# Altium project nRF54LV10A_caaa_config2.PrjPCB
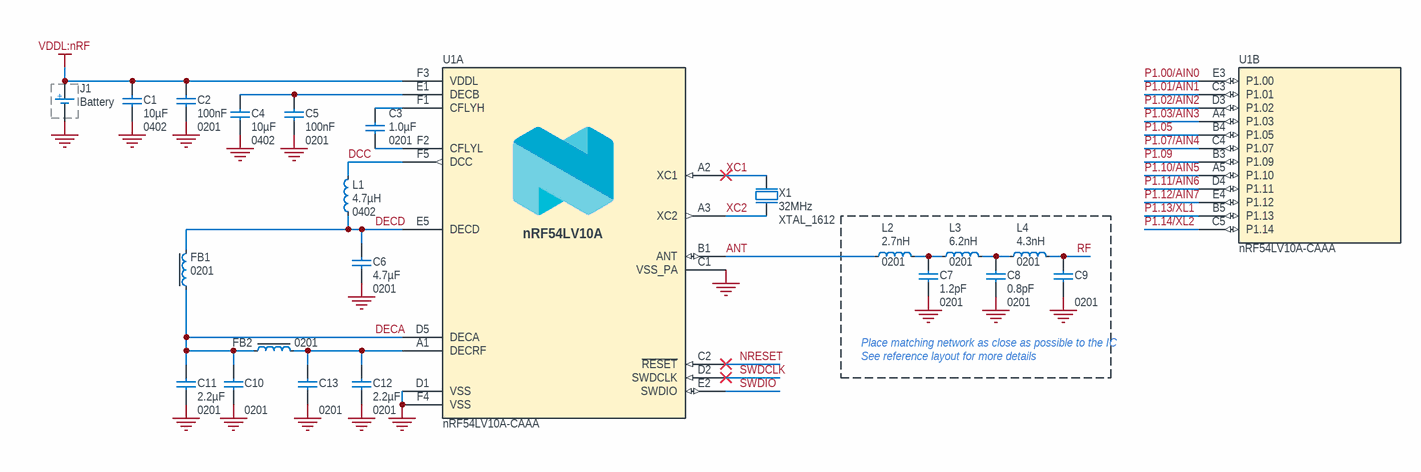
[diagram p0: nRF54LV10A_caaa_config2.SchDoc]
RefLayoutTitle: VDDL:nRF supplied by 1.5 V battery, Enabled DC/DC, 4-Layer PCB; Revision: 0.6; DrawnBy: DABA; Device: nRF54LV10A-CAAA; Config: 2; Classification: Public
1 sheet, 22 parts. Net scope: strictly hierarchical (ports join the sheet entries above them; power ports are local).
Board file: nRF54LV10A_caaa_config2.PcbDoc

## Sheet nRF54LV10A_caaa_config2.SchDoc
size A4; PCAName: Reference Layout; Organization: Nordic Semiconductor; SheetNumber: 1; SheetTotal: 1; DocumentSize: A4; Device: nRF54LV10A-CAAA; Classification: Confidential; Config: 2

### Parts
C1  10µF  Footprint Doc: 0402  [CAPC1005X04L]
C2  100nF  Footprint Doc: 0201  [CAPC0603X03L_C]
C3  1.0µF  Footprint Doc: 0201  [CAPC0603X03L_C]
C4  10µF  Footprint Doc: 0402  [CAPC1005X04L]
C5  100nF  Footprint Doc: 0201  [CAPC0603X03L_C]
C6  4.7µF  Footprint Doc: 0201  [CAPC0603X03L_C]
C7  1.2pF  Footprint Doc: 0201  [CAPC0603X03L_C]
C8  0.8pF  Footprint Doc: 0201  [CAPC0603X03L_C]
C9  Footprint Doc: 0201  [CAPC0603X03L_C]  (hidden comment: 0.3pF)
C10  Footprint Doc: 0201  [CAPC0603X03L_C]  (hidden comment: 2.2µF)
C11  Footprint Doc: 0201  [CAPC0603X03L_C]  (hidden comment: 2.2µF)
C12  Footprint Doc: 0201  [CAPC0603X03L_C]  (hidden comment: 2.2µF)
C13  Footprint Doc: 0201  [CAPC0603X03L_C]  (hidden comment: 2.2µF)
FB1  Footprint Doc: 0201  [INDC0603X03L_C]  (hidden comment: 120R/0.2A)
FB2  Footprint Doc: 0201  [INDC0603X03L_C]  (hidden comment: 120R/0.2A)
J1  Battery  [TP_2x1mm_TH]  (graphical)
L1  4.7µH  Footprint Doc: 0402  [INDDFN10X06X08L31X32L]
L2  2.7nH  Footprint Doc: 0201  [INDC0603X03L_C]
L3  6.2nH  Footprint Doc: 0201  [INDC0603X03L_C]
L4  4.3nH  Footprint Doc: 0201  [INDC0603X03L_C]
U1  nRF54LV10A-CAAA  [BGA29CP35_5X6_239X201X45B20]  (parts A,B of 2)
X1  32MHz  Footprint Doc: XTAL_1612  [BT-XTAL_1612]

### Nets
GND: C1.1 C2.2 C4.1 C5.2 C6.1 C7.1 C8.1 C9.1 C10.2 C11.1 C12.1 C13.2 J1.1(GND) U1.C1(VSS_PA) U1.D1(VSS) U1.F4(VSS) X1.2(GND) X1.4(GND)
VDDL:nRF: C1.2 C2.1 J1.2(V+) U1.F3(VDDL)
ANT: L2.1 U1.B1(ANT)
DCC: L1.2 U1.F5(DCC)
DECA: C10.1 C11.2 FB1.2 FB2.2 U1.D5(DECA)
DECD: C6.2 FB1.1 L1.1 U1.E5(DECD)
NRESET: U1.C2(~{RESET})
P1.00/AIN0: U1.E3(P1.00)
P1.01/AIN1: U1.C3(P1.01)
P1.02/AIN2: U1.D3(P1.02)
P1.03/AIN3: U1.A4(P1.03)
P1.05: U1.B4(P1.05)
P1.07/AIN4: U1.C4(P1.07)
P1.09: U1.B3(P1.09)
P1.10/AIN5: U1.A5(P1.10)
P1.11/AIN6: U1.D4(P1.11)
P1.12/AIN7: U1.E4(P1.12)
P1.13/XL1: U1.B5(P1.13)
P1.14/XL2: U1.C5(P1.14)
RF: C9.2 L4.2
SWDCLK: U1.D2(SWDCLK)
SWDIO: U1.E2(SWDIO)
XC1: U1.A2(XC1) X1.1(inp)
XC2: U1.A3(XC2) X1.3(out)
NetC3_1: C3.1 U1.F2(CFLYL)
NetC3_2: C3.2 U1.F1(CFLYH)
NetC4_2: C4.2 C5.1 U1.E1(DECB)
NetC7_2: C7.2 L2.2 L3.1
NetC8_2: C8.2 L3.2 L4.1
NetC12_2: C12.2 C13.1 FB2.1 U1.A1(DECRF)

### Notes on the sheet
- See reference layout for more details
- Place matching network as close as possible to the IC

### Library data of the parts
C1 C4 = C0402-10µF-6.3V-X6S: Capacitor, X6S, ±20%, 6.3V; Manufacturer: N.A.; Part number NEMS: 100200478; Component Status: Active; Pad Count: 2
C2 C5 = C0201-100n-10V-X7R: Capacitor, X7R, ±10%, 100nF, 10V; Manufacturer: N.A.; Part number NEMS: 100200469; Pad Count: 2; Component Status: Active
C3 = C0201-1µ0-6.3V: Capacitor, Ceramic, X5R, ±20%, 6.3V; Manufacturer: Murata; Manufacturer Part Number: GRM033R60J105MEA2D; Part number NEMS: 100200387; Component Status: Active; Pad Count: 2; Artikkelnr Noca: N.A.
C6 = C0201-4.7µ-6V3-X5R-GRM035R60J475ME15J: Capacitor, Ceramic, X5R, ±20%, 6.3V; Manufacturer: Murata; Part number NEMS: 100200685; Component Status: Active; Pad Count: 2; Note: -55°C ~ 85°C; Artikkelnr Noca: N.A.
C7 = C0201-1.2p-HQ-Murata: Capacitor, NP0, ±0.05pF, 50V; Manufacturer: Murata; Manufacturer Part Number: GJM0335C1H1R2WB01D; Part number NEMS: 100200457; Component Status: Active; Pad Count: 2; Artikkelnr Noca: N.A.
C8 = C0201-0.8p: Capacitor, NP0, ±0.05pF, 50V; Manufacturer: Murata; Manufacturer Part Number: GJM0335C1HR80WB01; Part number IPS: 80000001975; Part number NEMS: 100200012; Component Status: Active; Pad Count: 2; Artikkelnr Noca: N.A.
C9 = C0201-0.3p-50V-GRM0335C1HR30BA01: Capacitor, C0G, ±0.1pF, 50V; Manufacturer: Murata; Part number NEMS: 100200650; Component Status: Active; Pad Count: 2; Artikkelnr Noca: N.A.
C10-C13 = C0201-2µ2-2.5V-X6T-GRM033D80E225ME47D: Capacitor, Ceramic, 2.2µF 2.5V X6T 0201,±20%; Manufacturer: Murata; Part number NEMS: 100200527; Component Status: Active; Pad Count: 2; Note: 2.5V, 20%, X6T; Artikkelnr Noca: N.A.
FB1 FB2 = FB0201-120R@100M-200mA-BLM03AG121SN1D: Ferrite Bead, 120 Ohm @ 100MHz, 200mA, 500 mOhm Max; Manufacturer: Murata; Part number NEMS: 100300419; Component Status: Active; Pad Count: 2; Artikkelnr Noca: N.A.
J1 = Battery_TP: Manufacturer: N.A.; Part number NEMS: 101800006; Component Status: Active; Pad Count: 3
L1 = L0402-4µ7-PLEA67BCA4R7M-1PT00: Inductor, 300mA, ±20%, 1.08R; Manufacturer: TDK Corporation; Part number NEMS: 100300441; Component Status: Active; Pad Count: 2; Note: Power Inductor ±20%; Artikkelnr Noca: N.A.
L2 = L0201-2n7-HQ-Murata: Inductor, 600mA, ±0.1ｎH, 120mOhm; Manufacturer: Murata; Manufacturer Part Number: LQP03HQ2N7B02; Part number IPS: 00000001753; Part number NEMS: 100300214; Component Status: Active; Pad Count: 2; Note: -55°C ~ 125°C; Artikkelnr Noca: N.A.
L3 = L0201-6n2-HQ-Murata: Inductor, 400mA, ±3%, 250mOhm; Manufacturer: Murata; Manufacturer Part Number: LQP03HQ6N2H02; Part number NEMS: 100300237; Component Status: Active; Pad Count: 2; Note: -55°C ~ 125°C; Artikkelnr Noca: N.A.
L4 = L0201-4n3-HQ-Murata: Inductor, 500mA, ±3%, 170mOhm; Manufacturer: Murata; Manufacturer Part Number: LQP03HQ4N3H02; Part number NEMS: 100300230; Component Status: Active; Pad Count: 2; Note: -55°C ~ 125°C; Artikkelnr Noca: N.A.
U1 = nRF54LV10A-CAAA: Multi-protocol Bluetooth Low Energy, IEEE 802.15.4 and 2.4GHz proprietary Wireless MCU; Manufacturer: Nordic Semiconductor; Part number NEMS: 102000317; Component Status: Active; Pad Count: 29; Note: N.A.
X1 = XTAL_SMD1612_32MHz_8pF_Kyocera: XTAL SMD 1612, 32MHz, Cl=8pF, Tot: ±40ppm, Aging: ±1ppm/year; Manufacturer Part Number: CX1612DB32000D0WZRC3; Part number NEMS: 101600029; Component Status: Active; Pad Count: 4; Note: XTAL SMD 32.000MHz; Artikkelnr Noca: N.A.

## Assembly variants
Default: not fitted C9 C10 C13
